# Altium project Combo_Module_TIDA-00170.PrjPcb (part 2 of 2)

## Sheet Pg8 Analog Output.SchDoc
size 431 x 279 mm; Date: Not shown in title block; ApprovedBy: Not shown in title block; CheckedBy: Not shown in title block; Author: Not shown in title block; CompanyName: Not shown in title block; Engineer: Not shown in title block; Organization: Not shown in title block; Address1: Not shown in title block; Address2: Not shown in title block; Address3: Not shown in title block; Address4: Not shown in title block; DocumentNumber: 7; Revision: Use project parameter SCH_Rev; SheetNumber: 7; SheetTotal: 8; PageSetup: Record=PageOptions|CenterHorizontal=True|CenterVertical=True|PrintScale=1.00|XCorrection=1.00|YCorrection=1.00|PrintKind=0|BorderSize=5000000|LeftOffset=0|BottomOffset=0|Orientation=2|PaperLength=1000|PaperWidth=1000|Scale=100|PaperSource=15|PrintQuality=600|MediaType=1|DitherType=10|PaperKind=Letter|PrintScaleMode=1
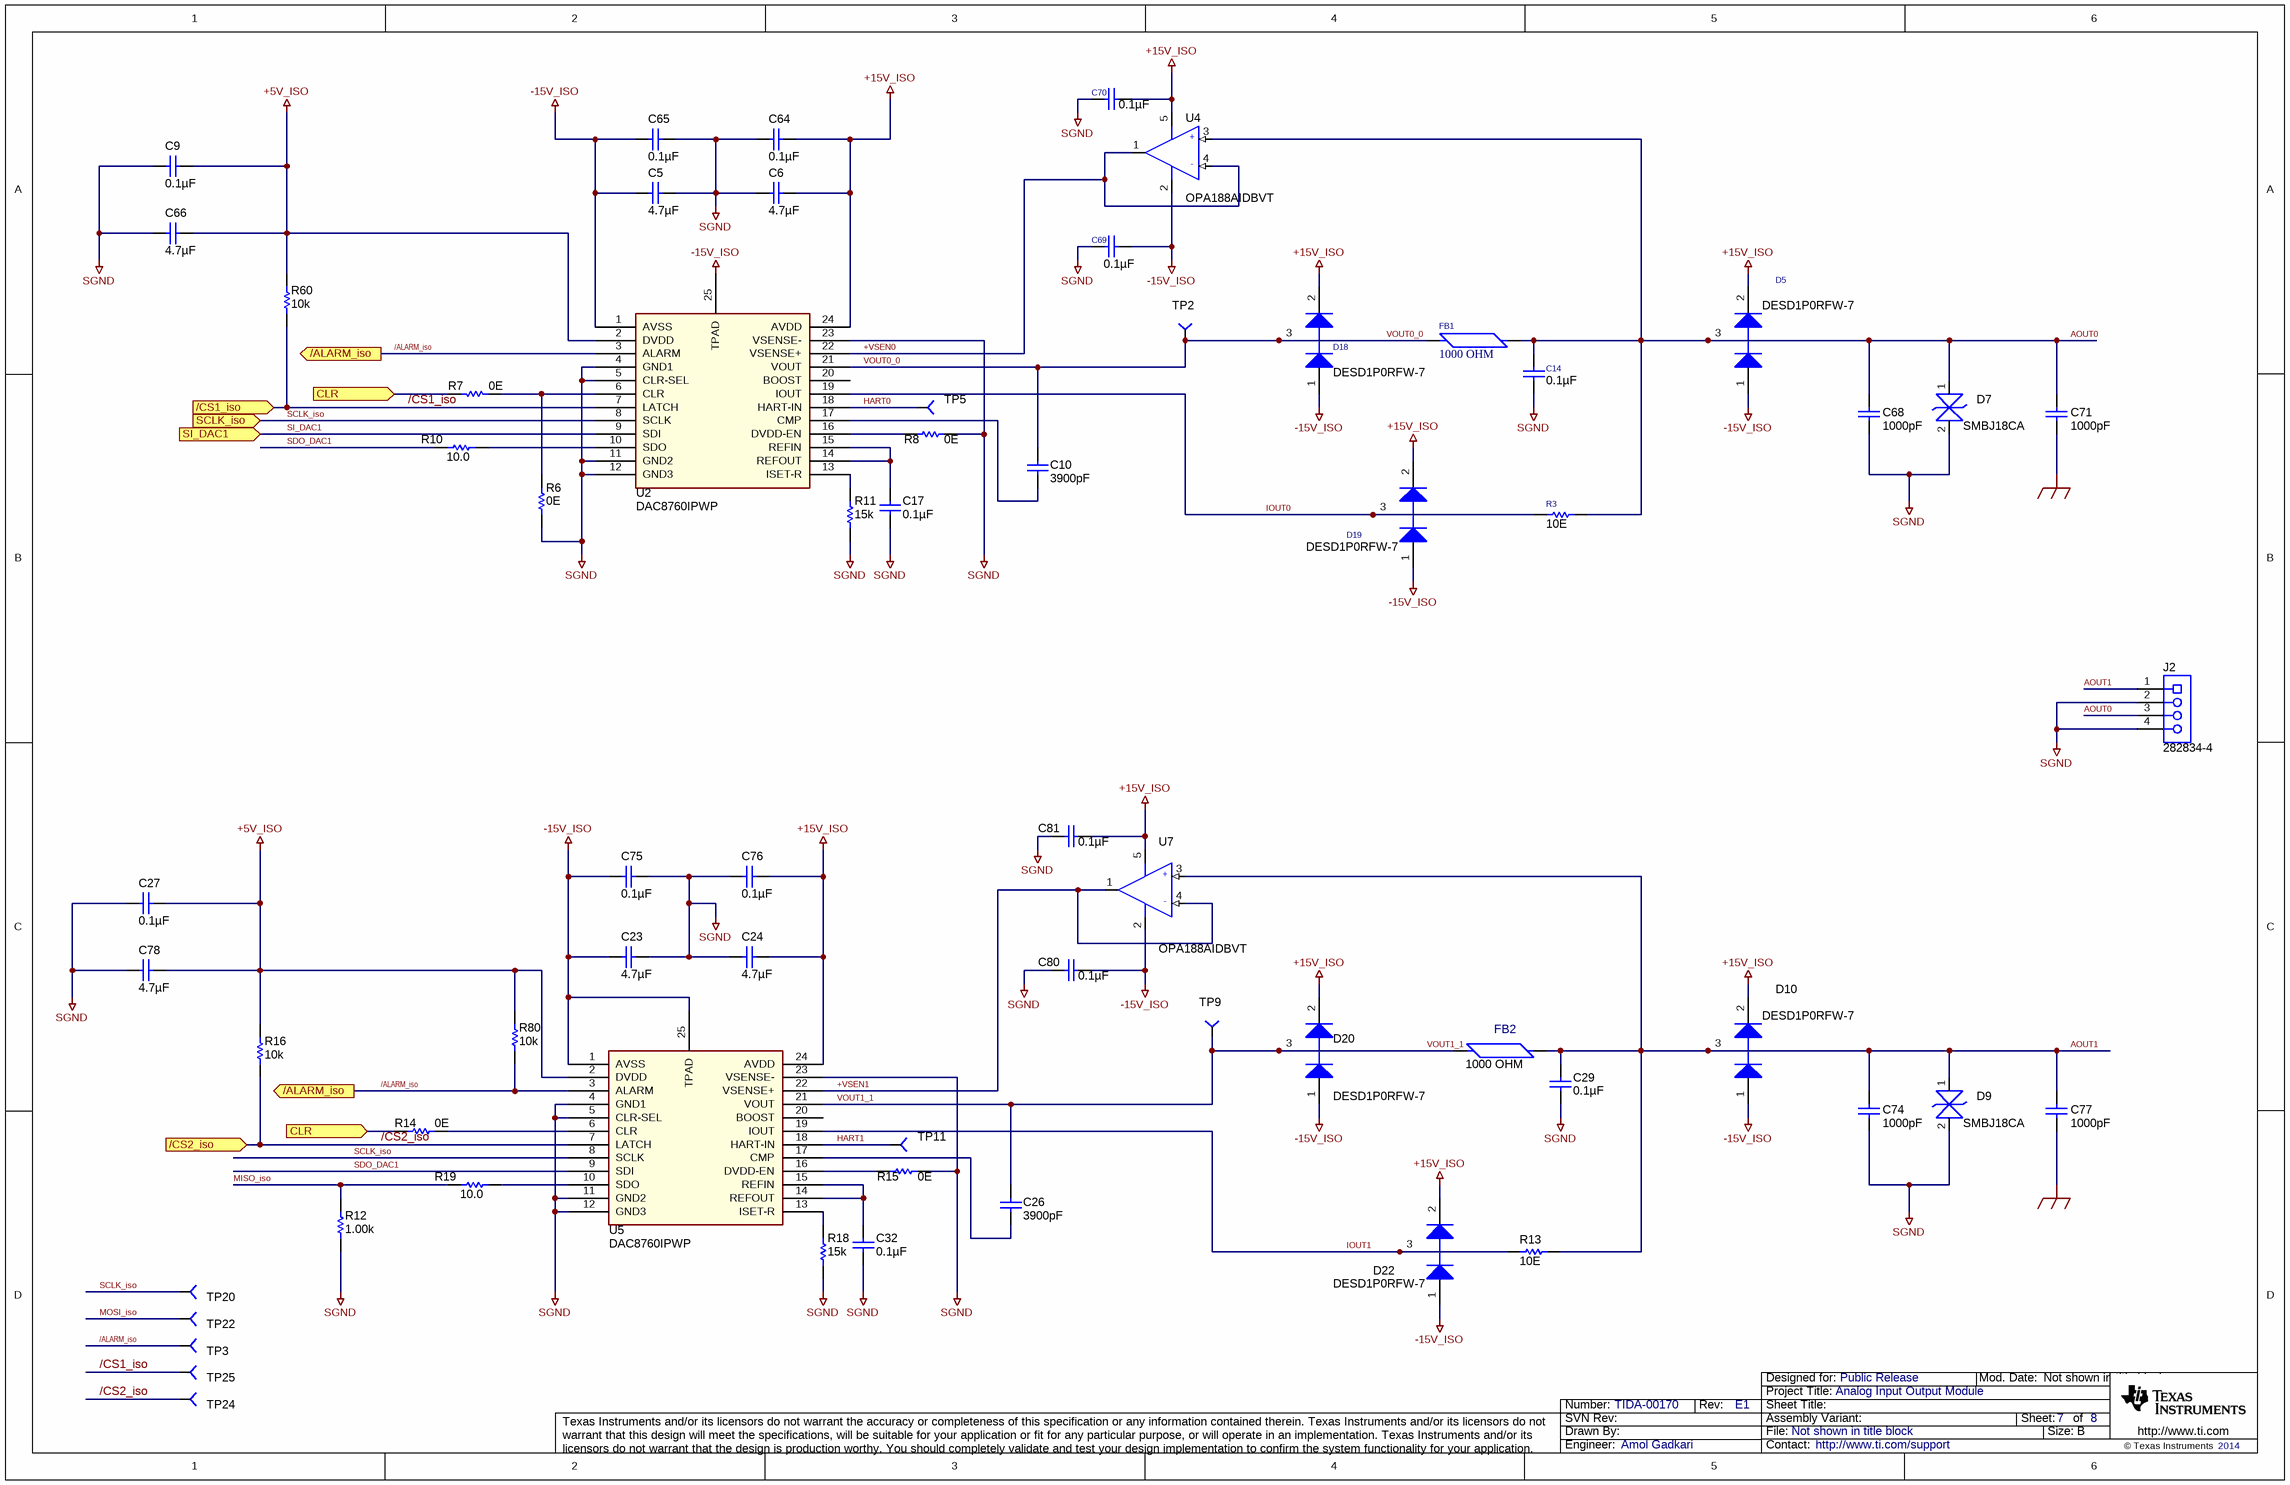
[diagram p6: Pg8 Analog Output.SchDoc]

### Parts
C5  ValueDisplayed: 4.7µF  [0805_HV]  (hidden comment: C2012X5R1H475K125AB)
C6  ValueDisplayed: 4.7µF  [0805_HV]  (hidden comment: C2012X5R1H475K125AB)
C9  ValueDisplayed: 0.1µF  [0603]  (hidden comment: 06035C104KAT2A)
C10  ValueDisplayed: 3900pF  [0603]  (hidden comment: GRM188R71H392KA01D)
C14  ValueDisplayed: 0.1µF  [0603]  (hidden comment: 06035C104KAT2A)
C17  ValueDisplayed: 0.1µF  [0603]  (hidden comment: 06035C104KAT2A)
C23  ValueDisplayed: 4.7µF  [0805_HV]  (hidden comment: C2012X5R1H475K125AB)
C24  ValueDisplayed: 4.7µF  [0805_HV]  (hidden comment: C2012X5R1H475K125AB)
C26  ValueDisplayed: 3900pF  [0603]  (hidden comment: GRM188R71H392KA01D)
C27  ValueDisplayed: 0.1µF  [0603]  (hidden comment: 06035C104KAT2A)
C29  ValueDisplayed: 0.1µF  [0603]  (hidden comment: 06035C104KAT2A)
C32  ValueDisplayed: 0.1µF  [0603]  (hidden comment: 06035C104KAT2A)
C64  ValueDisplayed: 0.1µF  [0603]  (hidden comment: 06035C104KAT2A)
C65  ValueDisplayed: 0.1µF  [0603]  (hidden comment: 06035C104KAT2A)
C66  ValueDisplayed: 4.7µF  [0805_HV]  (hidden comment: C2012X5R1H475K125AB)
C68  value 1000pF  [1206]  (hidden comment: 202R18W102KV4E)
C69  ValueDisplayed: 0.1µF  [0603]  (hidden comment: 06035C104KAT2A)
C70  ValueDisplayed: 0.1µF  [0603]  (hidden comment: 06035C104KAT2A)
C71  value 1000pF  [1206]  (hidden comment: 202R18W102KV4E)
C74  value 1000pF  [1206]  (hidden comment: 202R18W102KV4E)
C75  ValueDisplayed: 0.1µF  [0603]  (hidden comment: 06035C104KAT2A)
C76  ValueDisplayed: 0.1µF  [0603]  (hidden comment: 06035C104KAT2A)
C77  value 1000pF  [1206]  (hidden comment: 202R18W102KV4E)
C78  ValueDisplayed: 4.7µF  [0805_HV]  (hidden comment: C2012X5R1H475K125AB)
C80  ValueDisplayed: 0.1µF  [0603]  (hidden comment: 06035C104KAT2A)
C81  ValueDisplayed: 0.1µF  [0603]  (hidden comment: 06035C104KAT2A)
D5  DESD1P0RFW-7  [SOT-323]
D7  SMBJ18CA  [DIO_SMB_BIAAAA]
D9  SMBJ18CA  [DIO_SMB_BIAAAA]
D10  DESD1P0RFW-7  [SOT-323]
D18  DESD1P0RFW-7  [SOT-323]
D19  DESD1P0RFW-7  [SOT-323]
D20  DESD1P0RFW-7  [SOT-323]
D22  DESD1P0RFW-7  [SOT-323]
FB1  1000 OHM  [FB0603]
FB2  1000 OHM  [FB0603]
J2  282834-4  [TEC_282834-4]
R3  value 10E  [1206]  (hidden comment: CRCW120610R0JNEA)
R6  value 0E  [0402]  (hidden comment: CRCW04020000Z0ED)
R7  value 0E  [0402]  (hidden comment: CRCW04020000Z0ED)
R8  value 0E  [0402]  (hidden comment: CRCW04020000Z0ED)
R10  value 10.0  [0603]  (hidden comment: CRCW060310R0FKEA)
R11  value 15k  [0603]  (hidden comment: RT0603BRB0715KL)
R12  value 1.00k  [0603]  (hidden comment: CRCW06031K00FKEA)
R13  value 10E  [1206]  (hidden comment: CRCW120610R0JNEA)
R14  value 0E  [0402]  (hidden comment: CRCW04020000Z0ED)
R15  value 0E  [0402]  (hidden comment: CRCW04020000Z0ED)
R16  value 10k  [0402]  (hidden comment: CRCW040210K0JNED)
R18  value 15k  [0603]  (hidden comment: RT0603BRB0715KL)
R19  value 10.0  [0603]  (hidden comment: CRCW060310R0FKEA)
R60  value 10k  [0402]  (hidden comment: CRCW040210K0JNED)
R80  value 10k  [0402]  (hidden comment: CRCW040210K0JNED)
TP2  TP-038  [TP1_PD40_D0.5_S50]  (value not drawn)
TP3  TP-038  [TP1_PD40_D0.5_S50]  (value not drawn)
TP5  TP-038  [TP1_PD40_D0.5_S50]  (value not drawn)
TP9  TP-038  [TP1_PD40_D0.5_S50]  (value not drawn)
TP11  TP-038  [TP1_PD40_D0.5_S50]  (value not drawn)
TP20  TP-038  [TP1_PD40_D0.5_S50]  (value not drawn)
TP22  TP-038  [TP1_PD40_D0.5_S50]  (value not drawn)
TP24  TP-038  [TP1_PD40_D0.5_S50]  (value not drawn)
TP25  TP-038  [TP1_PD40_D0.5_S50]  (value not drawn)
U2  DAC8760IPWP  [PWP24-DIE84X166]
U4  OPA188AIDBVT  [DBV0005A_L]
U5  DAC8760IPWP  [PWP24-DIE84X166]
U7  OPA188AIDBVT  [DBV0005A_L]

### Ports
/ALARM_iso (out), /CS1_iso (in), /CS2_iso (in), CLR (in), SCLK_iso (in), SI_DAC1 (in)

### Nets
+5V_ISO: C9.2 C27.2 C66.2 C78.1 R16.2 R60.2 R80.2 U2.2(DVDD) U5.2(DVDD)
+15V_ISO: C6.2 C24.1 C64.1 C70.1 C76.2 C81.2 D5.2(K) D10.2(K) D18.2(K) D19.2(K) D20.2(K) D22.2(K) U2.24(AVDD) U4.5(VDD) U5.24(AVDD) U7.5(VDD)
-15V_ISO: C5.1 C23.2 C65.2 C69.1 C75.1 C80.2 D5.1(A) D10.1(A) D18.1(A) D19.1(A) D20.1(A) D22.1(A) U2.1(AVSS) U2.25(TPAD) U4.2(VSS) U5.1(AVSS) U5.25(TPAD) U7.2(VSS)
GND_EARTH: C71.2 C77.2
SGND: C5.2 C6.1 C9.1 C14.2 C17.1 C23.1 C24.2 C27.1 C29.2 C32.1 C64.2 C65.1 C66.1 C68.2 C69.2 C70.2 C74.2 C75.2 C76.1 C78.2 C80.1 C81.1 D7.2 D9.2 J2.2 J2.4 R6.2 R8.2 R11.2 R12.1 R15.2 R18.2 U2.4(GND1) U2.5(CLR-SEL) U2.11(GND2) U2.12(GND3) U2.23(VSENSE-) U5.4(GND1) U5.5(CLR-SEL) U5.11(GND2) U5.12(GND3) U5.23(VSENSE-)
+VSEN0: U2.22(VSENSE+) U4.1(OUT) U4.4(-)
+VSEN1: U5.22(VSENSE+) U7.1(OUT) U7.4(-)
/ALARM_iso: R80.1 TP3.1 U2.3(ALARM) U5.3(ALARM) ; port /ALARM_iso
/CS1_iso: R60.1 TP25.1 U2.7(LATCH) ; port /CS1_iso
/CS2_iso: R16.1 TP24.1 U5.7(LATCH) ; port /CS2_iso
AOUT0: C14.1 C68.1 C71.1 D5.3(C) D7.1 FB1.1 J2.3 R3.1 U4.3(+)
AOUT1: C29.1 C74.1 C77.1 D9.1 D10.3(C) FB2.1 J2.1 R13.1 U7.3(+)
CLR: R7.1 R14.1 ; port CLR
HART0: TP5.1 U2.18(HART-IN)
HART1: TP11.1 U5.18(HART-IN)
IOUT0: D19.3(C) R3.2 U2.19(IOUT)
IOUT1: D22.3(C) R13.2 U5.19(IOUT)
MISO_iso: R12.2 R19.1
MOSI_iso: TP22.1
SCLK_iso: TP20.1 U2.8(SCLK) U5.8(SCLK) ; port SCLK_iso
SDO_DAC1: R10.1 U5.9(SDI)
SI_DAC1: U2.9(SDI) ; port SI_DAC1
VOUT0_0: C10.1 D18.3(C) FB1.2 TP2.1 U2.21(VOUT)
VOUT1_1: C26.1 D20.3(C) FB2.2 TP9.1 U5.21(VOUT)
NetC10_2: C10.2 U2.17(CMP)
NetC17_2: C17.2 U2.14(REFOUT) U2.15(REFIN)
NetC26_2: C26.2 U5.17(CMP)
NetC32_2: C32.2 U5.14(REFOUT) U5.15(REFIN)
NetR6_1: R6.1 R7.2 U2.6(CLR)
NetR8_1: R8.1 U2.16(DVDD-EN)
NetR10_2: R10.2 U2.10(SDO)
NetR11_1: R11.1 U2.13(ISET-R)
NetR14_2: R14.2 U5.6(CLR)
NetR15_1: R15.1 U5.16(DVDD-EN)
NetR18_1: R18.1 U5.13(ISET-R)
NetR19_2: R19.2 U5.10(SDO)

Not connected (* = marked no-connect by the designer): U2 20(BOOST); U5 20(BOOST)

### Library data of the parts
C5 C6 C23 C24 C66 C78 = C2012X5R1H475K125AB: CAP, CERM, 4.7uF, 50V, +/-10%, X5R, 0805; Manufacturer: TDK; Polarized: N; CompType: Capacitor; U/M: EA; Cap_F: 0.0000047; Tolerance_%: 10; Value1: Unknown; VDC_V: 50; TaMin_C: -55; TaMax_C: 85; Cap_Case: 0805
C9 C14 C17 C27 C29 C32 C64 C65 C69 C70 C75 C76 C80 C81 = 06035C104KAT2A: CAP, CERM, 0.1uF, 50V, +/-10%, X7R, 0603; Manufacturer: AVX; Polarized: N; CompType: Capacitor; U/M: EA; Cap_F: 0.0000001; Tolerance_%: 10; Value1: Unknown; VDC_V: 50; TaMin_C: -55; TaMax_C: 125
C10 C26 = GRM188R71H392KA01D: CAP, CERM, 3900pF, 50V, +/-10%, X7R, 0603; Manufacturer: MuRata; Polarized: N; CompType: Capacitor; U/M: EA; Cap_F: 0.0000000039; Tolerance_%: 10; Value1: Unknown; VDC_V: 50; TaMin_C: -55; TaMax_C: 125
C68 C71 C74 C77 = 202R18W102KV4E: CAP, CERM, 1000pF, 2KV 10% X7R 1206; Manufacturer: Johanson Dielectrics Inc; Polarized: N; CompType: Capacitor; Cap_F: 0.000000001; Tolerance_%: 0
D5 D10 = BAV99WT1G: Diode, P-N, 70V, 0.2A, SOT-323; Manufacturer: Diodes Inc
D7 D9 = SMBJ18CA: TVS 18 VOLT 600 WATT BI-DIR SMB; Manufacturer: Littelfuse Inc
D18-D20 D22 = BAV99WT1G: Diode, P-N, 70V, 0.2A, SOT-323; Manufacturer: Diodes Inc; Value: DNP
FB1 FB2 = MMZ1608Y102B: FERRITE CHIP 1000 OHM 300MA 0603; Manufacturer: TDK Corporation; CompType: Ferrite Bead
J2 = 282834-4: Receptacle, 100mil, 4X1 TH; Manufacturer: TE Connectivity; SymbolCreator: a0411947; U/M: EA
R3 R13 = CRCW120610R0JNEA: RES, 10 ohm, 5%, 0.25W, 1206; Manufacturer: Vishay-Dale; CompType: Resistor; Res_ohm: 10; Value_Code: 10R0; Tolerance_%: 5; Power_W: 0.25; VDC_V: 200; TempCo: 200 ppm/C; EIA_Code: E24; U/M: EA
R6-R8 R14 R15 = CRCW04020000Z0ED: RES, 0 ohm, 5%, 0.063W, 0402; Manufacturer: Vishay-Dale; CompType: Resistor; Res_ohm: 0; Value_Code: 0000; Tolerance_%: 5; Power_W: 0.063; VDC_V: 50; TempCo: 200 ppm/C; EIA_Code: E24; U/M: EA
R10 R19 = CRCW060310R0FKEA: RES, 10.0 ohm, 1%, 0.1W, 0603; Manufacturer: Vishay-Dale; CompType: Resistor; Res_ohm: 10; Value_Code: 10R0; Tolerance_%: 1; Power_W: 0.1; VDC_V: 75; TempCo: 100 ppm/C; EIA_Code: E96; U/M: EA
R11 R18 = RT0603BRB0715KL: RES, 15k ohm, 1/10W 0.1% 0603; Manufacturer: Vishay-Dale; CompType: Resistor; Res_ohm: 15000; Tolerance_%: 0.1; Power_W: 1/10
R12 = CRCW06031K00FKEA: RES, 1.00k ohm, 1%, 0.1W, 0603; Manufacturer: Vishay-Dale; CompType: Resistor; Res_ohm: 1000; Value_Code: 1k00; Tolerance_%: 1; Power_W: 0.1; VDC_V: 75; TempCo: 100 ppm/C; EIA_Code: E96; U/M: EA
R16 R60 R80 = CRCW040210K0JNED: RES, 10k ohm, 5%, 0.063W, 0402; Manufacturer: Vishay-Dale; CompType: Resistor; Res_ohm: 10000; Value_Code: 10k0; Tolerance_%: 5; Power_W: 0.063; VDC_V: 50; TempCo: 200 ppm/C; EIA_Code: E24; U/M: EA
TP2 TP3 TP5 TP9 TP11 TP20 TP22 TP24 TP25 = TP-038: Test Point 40mil pad 20mil drill; Manufacturer: STD; Value: STD
U2 U5 = DAC8760IPWP: 1-Channel, 16-Bit, Programmable Current/Voltage Output DAC for 4-20mA Current Loop Applications; Manufacturer: Texas Instruments; CompType: IC; SymbolCreator: x0120606
U4 U7 = OPA188AIDBVT: Precision, Low Noise, Rail-to-Rail Output, 36V Zero-Drift Operational Amplifier; Manufacturer: Texas Instruments; CompType: IC

## Sheet Pg9 Hardware.SchDoc
size 431 x 279 mm; Date: Not shown in title block; ApprovedBy: Not shown in title block; CheckedBy: Not shown in title block; Author: Not shown in title block; CompanyName: Not shown in title block; Engineer: Not shown in title block; Organization: Not shown in title block; Address1: Not shown in title block; Address2: Not shown in title block; Address3: Not shown in title block; Address4: Not shown in title block; DocumentNumber: 8; Revision: Use project parameter SCH_Rev; SheetNumber: 8; SheetTotal: 8; PageSetup: Record=PageOptions|CenterHorizontal=True|CenterVertical=True|PrintScale=1.00|XCorrection=1.00|YCorrection=1.00|PrintKind=0|BorderSize=5000000|LeftOffset=0|BottomOffset=0|Orientation=2|PaperLength=1000|PaperWidth=1000|Scale=100|PaperSource=15|PrintQuality=600|MediaType=1|DitherType=10|PaperKind=Letter|PrintScaleMode=1
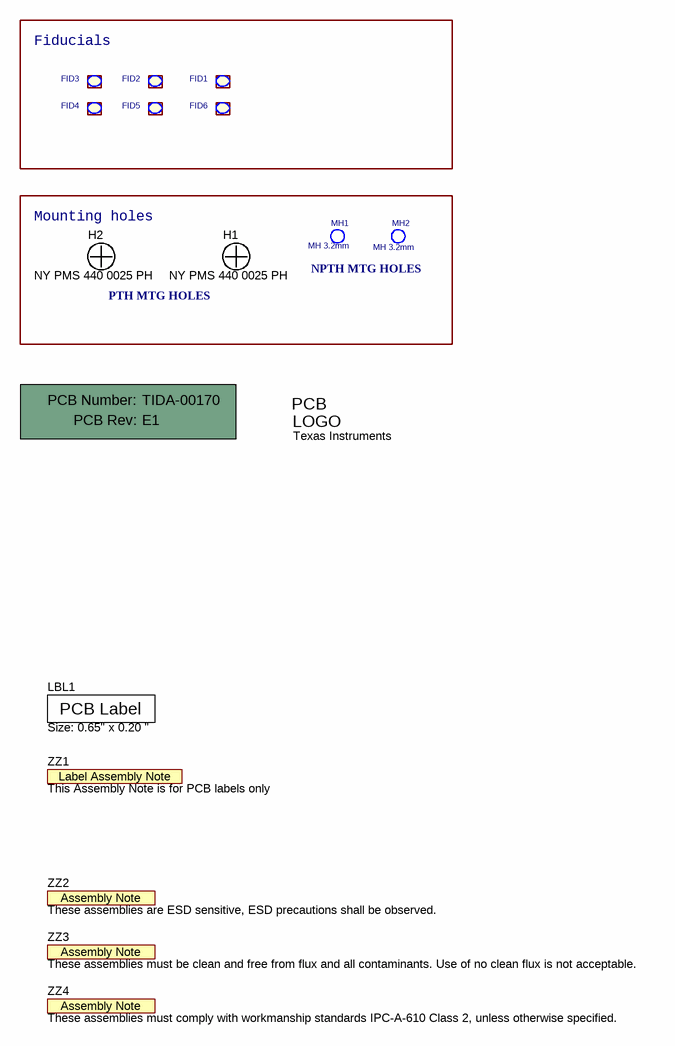
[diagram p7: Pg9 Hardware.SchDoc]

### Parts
!PCB  Printed Circuit Board  (value not drawn)  (mechanical)
FID1  Fiducial40_80  [FID_TOP_40_80BA]  (value not drawn)
FID2  Fiducial40_80  [FID_TOP_40_80BA]  (value not drawn)
FID3  Fiducial40_80  [FID_TOP_40_80BA]  (value not drawn)
FID4  Fiducial40_80  [FID_TOP_40_80BA]  (value not drawn)
FID5  Fiducial40_80  [FID_TOP_40_80BA]  (value not drawn)
FID6  Fiducial40_80  [FID_TOP_40_80BA]  (value not drawn)
H1  NY PMS 440 0025 PH  [NY PMS 440 0025 PH]
H2  NY PMS 440 0025 PH  [NY PMS 440 0025 PH]
LBL1  Size: 0.65" x 0.20 "  [Label_650x200]
Logo1  Texas Instruments  [TI_Stacked_SolderMask_Small]  (no BOM)
MH1  MH 3.2mm  [MH3.2_H5_W6_KO8_STARHEAD]
MH2  MH 3.2mm  [MH3.2_H5_W6_KO8_STARHEAD]
ZZ1  This Assembly Note is for PCB labels only  [AssemblyNoteLabel]  (no BOM)
ZZ2  These assemblies are ESD sensitive, ESD precautions shall be observed.  [AssemblyNote]  (no BOM)
ZZ3  These assemblies must be clean and free from flux and all contaminants. Use of no clean flux is not acceptable.  [AssemblyNote]  (no BOM)
ZZ4  These assemblies must comply with workmanship standards IPC-A-610 Class 2, unless otherwise specified.  [AssemblyNote]  (no BOM)

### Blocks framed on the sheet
Fiducials: FID1-FID6
Mounting holes: H1 H2 MH1 MH2

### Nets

Not connected (* = marked no-connect by the designer): FID1 1; FID2 1; FID3 1; FID4 1; FID5 1; FID6 1; MH1 1; MH2 1

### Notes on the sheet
- (near H2) PTH MTG HOLES
- NPTH MTG HOLES

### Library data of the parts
!PCB = PCB: Manufacturer: Any; PartNumber: TIDA-00170; SymbolCreator: a0412235
FID1-FID6 = Fiducial40_0
H1 H2 = NY PMS 440 0025 PH: Machine Screw, Round, #4-40 x 1/4, Nylon, Philips panhead; Manufacturer: B&F Fastener Supply; CompType: Hardware; SymbolCreator: codlsc; U/M: EA
LBL1 = THT-14-423-10: Thermal Transfer Printable Labels, 0.650" W x 0.200" H - 10,000 per roll; Manufacturer: Brady; SymbolCreator: a0412235; CompType: Label
Logo1 = TI_Logo: Texas Instrument Corporate Signature; SymbolCreator: codlsc
MH1 MH2 = MH 3_0.5MM: Mountin hole, NPTH Drill 3.2mm
ZZ1 = AssemblyNoteLabel: SymbolCreator: a0412235
ZZ2-ZZ4 = AssemblyNote: SymbolCreator: codlsc

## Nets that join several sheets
+3.3V_NON_ISO: Pg3 Interboard conn, HS & EEPROM (C55.2 R76.1 R77.1 U19.8), Pg4 ISO Power Supply, I2C & SPI Isolators (9 pins)
+5V_ISO: Pg4 ISO Power Supply, I2C & SPI Isolators (10 pins), Pg5 LDO (6 pins), Pg6 ADC (10 pins), Pg8 Analog Output (9 pins)
+6V_ISO: Pg4 ISO Power Supply, I2C & SPI Isolators (C35.1 D12.1 TP14.1), Pg5 LDO (C42.1 C47.2 U11.5 U11.8)
+15V_ISO: Pg5 LDO (6 pins), Pg8 Analog Output (16 pins)
+18V_ISO: Pg4 ISO Power Supply, I2C & SPI Isolators (C34.1 D13.1 TP13.1), Pg5 LDO (C33.1 U6.13 U6.15 U6.16)
+24VDC_LIMIT: Pg3 Interboard conn, HS & EEPROM (6 pins), Pg4 ISO Power Supply, I2C & SPI Isolators (L2.1)
-15V_ISO: Pg5 LDO (6 pins), Pg6 ADC (R67.1 R69.1 R74.1 R78.1), Pg8 Analog Output (18 pins)
-18V_ISO: Pg4 ISO Power Supply, I2C & SPI Isolators (C3.2 D3.2 TP1.1), Pg5 LDO (C4.1 C11.2 U1.5 U1.8)
GND: Pg3 Interboard conn, HS & EEPROM (23 pins), Pg4 ISO Power Supply, I2C & SPI Isolators (21 pins)
GND_EARTH: Pg6 ADC (7 pins), Pg8 Analog Output (C71.2 C77.2)
SGND: Pg4 ISO Power Supply, I2C & SPI Isolators (15 pins), Pg5 LDO (37 pins), Pg6 ADC (52 pins), Pg8 Analog Output (42 pins)
/ALARM: Pg3 Interboard conn, HS & EEPROM (J5.6), Pg4 ISO Power Supply, I2C & SPI Isolators (U18.2)
/ALARM_iso: Pg4 ISO Power Supply, I2C & SPI Isolators (TP26.1 U18.7), Pg8 Analog Output (R80.1 TP3.1 U2.3 U5.3)
/CS0: Pg3 Interboard conn, HS & EEPROM (J5.1), Pg4 ISO Power Supply, I2C & SPI Isolators (U15.3)
/CS0_iso: Pg4 ISO Power Supply, I2C & SPI Isolators (U15.14), Pg6 ADC (TP18.1 U13.38)
/CS1_iso: Pg4 ISO Power Supply, I2C & SPI Isolators (U17.5), Pg8 Analog Output (R60.1 TP25.1 U2.7)
/CS2_iso: Pg4 ISO Power Supply, I2C & SPI Isolators (U17.6), Pg8 Analog Output (R16.1 TP24.1 U5.7)
CLR: Pg4 ISO Power Supply, I2C & SPI Isolators (U17.7), Pg8 Analog Output (R7.1 R14.1)
MISO: Pg3 Interboard conn, HS & EEPROM (J5.5), Pg4 ISO Power Supply, I2C & SPI Isolators (U15.6)
MISO_iso: Pg4 ISO Power Supply, I2C & SPI Isolators (U15.11), Pg6 ADC (R38.2 TP23.1)
MOSI: Pg3 Interboard conn, HS & EEPROM (J5.7), Pg4 ISO Power Supply, I2C & SPI Isolators (U15.5)
MOSI_iso: Pg4 ISO Power Supply, I2C & SPI Isolators (U15.12 U17.14), Pg6 ADC (R45.1)
OPTO_AN0: Pg4 ISO Power Supply, I2C & SPI Isolators (U17.4), Pg6 ADC (R56.1)
OPTO_AN1: Pg4 ISO Power Supply, I2C & SPI Isolators (U17.3), Pg6 ADC (R43.1)
OPTO_AN2: Pg4 ISO Power Supply, I2C & SPI Isolators (U17.2), Pg6 ADC (R34.1)
OPTO_AN3: Pg4 ISO Power Supply, I2C & SPI Isolators (U17.1), Pg6 ADC (R26.1)
RCLK: Pg3 Interboard conn, HS & EEPROM (J5.26), Pg4 ISO Power Supply, I2C & SPI Isolators (U18.3)
SCLK: Pg3 Interboard conn, HS & EEPROM (J5.3), Pg4 ISO Power Supply, I2C & SPI Isolators (U15.4)
SCLK_iso: Pg4 ISO Power Supply, I2C & SPI Isolators (R42.2 U17.11), Pg6 ADC (U13.37), Pg8 Analog Output (TP20.1 U2.8 U5.8)
SI_DAC1: Pg4 ISO Power Supply, I2C & SPI Isolators (R49.2 U17.9), Pg8 Analog Output (U2.9)

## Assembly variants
001: not fitted C38 C63 D2 D18 D19 D20 D22 R7 R12 R14 R73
